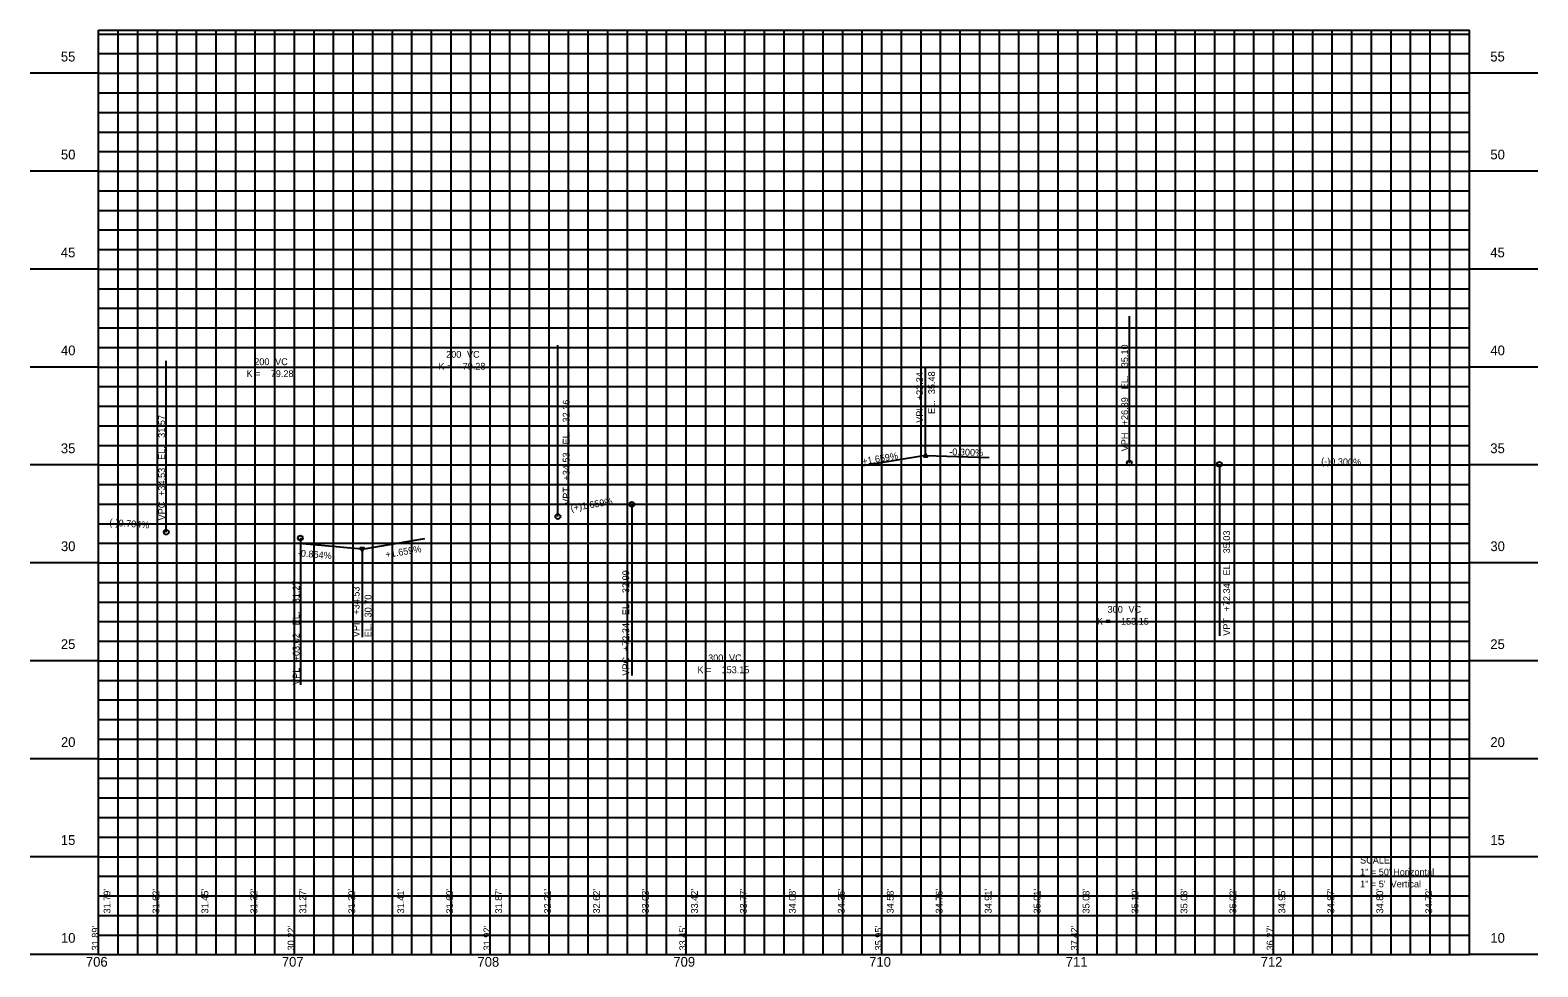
# Model space of a CAD drawing. Extents: x 665 to 1435, y 4 to 482.
import ezdxf

# ---------------------------------------------------------------- set-up
doc = ezdxf.new("R2010")
doc.units = 0
for name, color, linetype in [('TextAlgnStation100', 7, 'Continuous'), ('TextAlgnStation500', 7, 'Continuous'), ('TextAlgnStation5000', 7, 'Continuous'), ('TextAlgnTicks100', 7, 'Continuous'), ('TextAlgnTicks500', 7, 'Continuous')]:
    doc.layers.add(name, color=color, linetype=linetype)

msp = doc.modelspace()

# ---------------------------------------------------------------- linework, layer by layer
at = {"layer": 'TextAlgnStation100'}
for p, q in [((700, 482), (1400, 482)), ((700, 10), (700, 482)), ((700, 10), (700, 482)), ((750, 10), (750, 482)), ((800, 10), (800, 482)), ((850, 10), (850, 482)), ((900, 10), (900, 482)), ((950, 10), (950, 482)), ((1000, 10), (1000, 482)), ((1050, 10), (1050, 482)), ((1100, 10), (1100, 482)), ((1150, 10), (1150, 482)), ((1200, 10), (1200, 482)), ((1250, 10), (1250, 482)), ((1300, 10), (1300, 482)), ((1350, 10), (1350, 482)), ((1400, 10), (1400, 482)), ((700, 460), (665.02, 460)), ((700, 460), (1400, 460)), ((1434.98, 460), (1400, 460)), ((700, 410), (665.02, 410)), ((700, 410), (1400, 410)), ((1434.98, 410), (1400, 410)), ((700, 360), (665.02, 360)), ((700, 360), (1400, 360)), ((1434.98, 360), (1400, 360)), ((700, 310), (665.02, 310)), ((700, 310), (1400, 310)), ((1434.98, 310), (1400, 310)), ((700, 260), (665.02, 260)), ((700, 260), (1400, 260)), ((1434.98, 260), (1400, 260)), ((700, 210), (665.02, 210)), ((700, 210), (1400, 210)), ((1434.98, 210), (1400, 210)), ((700, 160), (665.02, 160)), ((700, 160), (1400, 160)), ((1434.98, 160), (1400, 160)), ((700, 110), (665.02, 110)), ((700, 110), (1400, 110)), ((1434.98, 110), (1400, 110)), ((700, 60), (665.02, 60)), ((700, 60), (1400, 60)), ((1434.98, 60), (1400, 60)), ((700, 10), (665.02, 10)), ((700, 10), (1400, 10)), ((1434.98, 10), (1400, 10))]:
    msp.add_line(p, q, dxfattribs=at)
at = {"layer": 'TextAlgnStation500'}
for p, q in [((1226.39, 260.98), (1226.39, 335.98)), ((934.53, 233.64), (934.53, 321.12)), ((934.53, 321.12), (934.53, 321.12)), ((734.53, 225.68), (734.53, 313.16)), ((734.53, 313.16), (734.53, 313.16)), ((1122.34, 264.79), (1090.28, 259.47)), ((1122.34, 264.79), (1154.82, 263.81)), ((1226.39, 268.48), (1226.39, 268.48)), ((1272.34, 260.29), (1272.34, 172.81)), ((972.34, 239.91), (972.34, 152.43)), ((834.53, 217.05), (802.15, 219.84)), ((803.02, 222.73), (803.02, 147.73)), ((834.53, 217.05), (866.59, 222.37)), ((834.53, 217.05), (834.53, 217.05)), ((803.02, 215.23), (803.02, 215.23)), ((1272.34, 172.81), (1272.34, 172.81)), ((972.34, 152.43), (972.34, 152.43))]:
    msp.add_line(p, q, dxfattribs=at)
for centre in [(1226.39, 260.98), (1272.34, 260.29), (972.34, 239.91), (934.53, 233.64), (734.53, 225.68), (803.02, 222.73)]:
    msp.add_circle(centre, 1.25, dxfattribs=at)
at = {"layer": 'TextAlgnStation5000'}
for p, q in [((1122.34, 264.79), (1122.34, 309.79)), ((834.53, 217.05), (834.53, 172.05))]:
    msp.add_line(p, q, dxfattribs=at)
for points in [[(1122.34, 265.94), (1121.34, 264.21), (1123.34, 264.21)], [(834.53, 215.9), (835.52, 217.62), (833.54, 217.62)]]:
    msp.add_lwpolyline(points, close=True, dxfattribs=at)
at = {"layer": 'TextAlgnTicks100'}
for p, q in [((700, 480), (1400, 480)), ((710, 10), (710, 482)), ((720, 10), (720, 482)), ((730, 10), (730, 482)), ((740, 10), (740, 482)), ((760, 10), (760, 482)), ((770, 10), (770, 482)), ((780, 10), (780, 482)), ((790, 10), (790, 482)), ((810, 10), (810, 482)), ((820, 10), (820, 482)), ((830, 10), (830, 482)), ((840, 10), (840, 482)), ((860, 10), (860, 482)), ((870, 10), (870, 482)), ((880, 10), (880, 482)), ((890, 10), (890, 482)), ((910, 10), (910, 482)), ((920, 10), (920, 482)), ((930, 10), (930, 482)), ((940, 10), (940, 482)), ((960, 10), (960, 482)), ((970, 10), (970, 482)), ((980, 10), (980, 482)), ((990, 10), (990, 482)), ((1010, 10), (1010, 482)), ((1020, 10), (1020, 482)), ((1030, 10), (1030, 482)), ((1040, 10), (1040, 482)), ((1060, 10), (1060, 482)), ((1070, 10), (1070, 482)), ((1080, 10), (1080, 482)), ((1090, 10), (1090, 482)), ((1110, 10), (1110, 482)), ((1120, 10), (1120, 482)), ((1130, 10), (1130, 482)), ((1140, 10), (1140, 482)), ((1160, 10), (1160, 482)), ((1170, 10), (1170, 482)), ((1180, 10), (1180, 482)), ((1190, 10), (1190, 482)), ((1210, 10), (1210, 482)), ((1220, 10), (1220, 482)), ((1230, 10), (1230, 482)), ((1240, 10), (1240, 482)), ((1260, 10), (1260, 482)), ((1270, 10), (1270, 482)), ((1280, 10), (1280, 482)), ((1290, 10), (1290, 482)), ((1310, 10), (1310, 482)), ((1320, 10), (1320, 482)), ((1330, 10), (1330, 482)), ((1340, 10), (1340, 482)), ((1360, 10), (1360, 482)), ((1370, 10), (1370, 482)), ((1380, 10), (1380, 482)), ((1390, 10), (1390, 482)), ((700, 470), (1400, 470)), ((700, 450), (1400, 450)), ((700, 440), (1400, 440)), ((700, 430), (1400, 430)), ((700, 420), (1400, 420)), ((700, 400), (1400, 400)), ((700, 390), (1400, 390)), ((700, 380), (1400, 380)), ((700, 370), (1400, 370)), ((700, 350), (1400, 350)), ((700, 340), (1400, 340)), ((700, 330), (1400, 330)), ((700, 320), (1400, 320)), ((700, 300), (1400, 300)), ((700, 290), (1400, 290)), ((700, 280), (1400, 280)), ((700, 270), (1400, 270)), ((700, 250), (1400, 250)), ((700, 240), (1400, 240)), ((700, 230), (1400, 230)), ((700, 220), (1400, 220)), ((700, 200), (1400, 200)), ((700, 190), (1400, 190)), ((700, 180), (1400, 180)), ((700, 170), (1400, 170)), ((700, 150), (1400, 150)), ((700, 140), (1400, 140)), ((700, 130), (1400, 130)), ((700, 120), (1400, 120)), ((700, 100), (1400, 100)), ((700, 90), (1400, 90)), ((700, 80), (1400, 80)), ((700, 70), (1400, 70)), ((700, 50), (1400, 50)), ((700, 40), (1400, 40)), ((700, 30), (1400, 30)), ((700, 20), (1400, 20))]:
    msp.add_line(p, q, dxfattribs=at)

# ---------------------------------------------------------------- texts
at = {"layer": 'TextAlgnStation500'}
for s, rotation, p in [('35.10', 90, (1225.73, 309.89)), (' EL. ', 90, (1225.73, 297.33)), ('32.36', 90, (940.52, 281.7)), ('+26.39', 90, (1225.73, 280.24)), ('31.57', 90, (733.92, 273.84)), (' EL. ', 90, (940.52, 269.15)), ('VPH ', 90, (1225.73, 266.98)), (' EL. ', 90, (733.92, 261.29)), ('+34.53', 90, (940.52, 252.05)), ('+1.659%', 9.41864, (1090.18, 260.07)), ('-0.300%', 358.28164, (1134.35, 265.04)), ('+34.53', 90, (733.92, 244.19)), ('VPT ', 90, (940.52, 239.64)), ('VPC ', 90, (733.92, 231.68)), ('35.03', 90, (1277.8, 214.86)), ('-0.864%', 355.06311, (801.59, 213.38)), ('+1.659%', 9.41864, (846.78, 212.5)), (' EL. ', 90, (1277.8, 202.3)), ('31.27', 90, (802.59, 189.38)), ('32.99', 90, (970.96, 194.59)), ('+72.34', 90, (1277.8, 185.21)), (' EL. ', 90, (970.96, 182.03)), (' EL. ', 90, (802.59, 176.83)), ('+72.34', 90, (970.96, 164.94)), ('VPT ', 90, (1277.8, 172.79)), ('+03.02', 90, (802.59, 159.73)), ('VPC ', 90, (970.96, 152.43)), ('VPL ', 90, (802.59, 147.73))]:
    msp.add_text(s, height=3.48, rotation=rotation, dxfattribs=at).set_placement(p)
for s, p in [('SCALE', (1344.2, 56.5)), ('1" = 50\' Horizontal', (1344.2, 50.41)), ('1" = 5\'  Vertical', (1344.2, 44.32))]:
    msp.add_text(s, height=3.48, dxfattribs=at).set_placement(p)
at = {"layer": 'TextAlgnStation5000'}
for s, p in [('200', (877.45, 314.73)), (' VC', (886.82, 314.73)), ('K = ', (775.55, 304.87)), ('200', (779.45, 310.96)), ('79.28', (787.87, 304.87)), (' VC', (788.82, 310.96)), ('K = ', (873.55, 308.64)), ('79.28', (885.87, 308.64)), ('300', (1215.25, 184.54)), (' VC', (1224.63, 184.54)), ('K = ', (1209.8, 178.45)), ('153.15', (1222.12, 178.45)), ('300', (1011.25, 159.75)), (' VC', (1020.63, 159.75)), ('K = ', (1005.8, 153.66)), ('153.15', (1018.12, 153.66))]:
    msp.add_text(s, height=3.48, dxfattribs=at).set_placement(p)
for s, p in [('+22.34', (1121.03, 293.04)), ('35.48', (1127.12, 296.15)), ('EL. ', (1127.12, 286.03)), ('VPI ', (1121.03, 281.54)), ('+34.53', (833.23, 183.55)), ('30.70', (839.32, 182.16)), ('VPI ', (833.23, 172.05)), ('EL. ', (839.32, 172.05))]:
    msp.add_text(s, height=3.48, rotation=90, dxfattribs=at).set_placement(p)
at = {"layer": 'TextAlgnTicks500'}
for s, p in [('55', (680.7, 466.01)), ('55', (1410.7, 466.01)), ('50', (680.74, 416.01)), ('50', (1410.74, 416.01)), ('45', (680.7, 366.01)), ('45', (1410.7, 366.01)), ('40', (680.74, 316.01)), ('40', (1410.74, 316.01)), ('35', (680.7, 266.01)), ('35', (1410.7, 266.01)), ('30', (680.74, 216.01)), ('30', (1410.74, 216.01)), ('25', (680.7, 166.01)), ('25', (1410.7, 166.01)), ('20', (680.74, 116.01)), ('20', (1410.74, 116.01)), ('15', (680.7, 66.01)), ('15', (1410.7, 66.01)), ('10', (680.74, 16.01)), ('10', (1410.74, 16.01)), ('706', (693.49, 3.82)), ('707', (793.55, 3.82)), ('708', (893.45, 3.82)), ('709', (993.49, 3.82)), ('710', (1093.5, 3.82)), ('711', (1193.89, 3.82)), ('712', (1293.44, 3.82))]:
    msp.add_text(s, height=4.98, dxfattribs=at).set_placement(p)
for s, height, rotation, p in [('(-)0.300%', 3.48, 358.28164, (1324.26, 260.23)), ('(+)1.659%', 3.48, 9.41864, (941.35, 236.27)), ('(-)0.704%', 3.48, 355.97423, (705.41, 229.03)), ("31.79'", 3.48, 90, (706, 31)), ("31.62'", 3.48, 90, (731, 31)), ("31.45'", 3.48, 90, (756, 31)), ("31.32'", 3.48, 90, (781, 31)), ("31.27'", 3.48, 90, (806, 31)), ("31.30'", 3.48, 90, (831, 31)), ("31.41'", 3.48, 90, (856, 31)), ("31.60'", 3.48, 90, (881, 31)), ("31.87'", 3.48, 90, (906, 31)), ("32.21'", 3.48, 90, (931, 31)), ("32.62'", 3.48, 90, (956, 31)), ("33.03'", 3.48, 90, (981, 31)), ("33.42'", 3.48, 90, (1006, 31)), ("33.77'", 3.48, 90, (1031, 31)), ("34.08'", 3.48, 90, (1056, 31)), ("34.35'", 3.48, 90, (1081, 31)), ("34.58'", 3.48, 90, (1106, 31)), ("34.76'", 3.48, 90, (1131, 31)), ("34.91'", 3.48, 90, (1156, 31)), ("35.01'", 3.48, 90, (1181, 31)), ("35.08'", 3.48, 90, (1206, 31)), ("35.10'", 3.48, 90, (1231, 31)), ("35.08'", 3.48, 90, (1256, 31)), ("35.02'", 3.48, 90, (1281, 31)), ("34.95'", 3.48, 90, (1306, 31)), ("34.87'", 3.48, 90, (1331, 31)), ("34.80'", 3.48, 90, (1356, 31)), ("34.72'", 3.48, 90, (1381, 31)), ("31.89'", 3.5, 90, (700.03, 12.1)), ("30.22'", 3.5, 90, (800.02, 12.1)), ("31.92'", 3.5, 90, (900.04, 12.1)), ("33.45'", 3.5, 90, (1000.05, 12.1)), ("35.95'", 3.5, 90, (1100.03, 12.1)), ("37.42'", 3.5, 90, (1200.02, 12.1)), ("36.27'", 3.5, 90, (1300.02, 12.1))]:
    msp.add_text(s, height=height, rotation=rotation, dxfattribs=at).set_placement(p)

doc.saveas('drawing.dxf')
